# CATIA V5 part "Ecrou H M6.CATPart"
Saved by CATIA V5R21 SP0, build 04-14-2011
Part number: Ecrou H M6
Material "Acier": density 7860 kg/m3, Young's modulus 2e+11 Pa, Poisson ratio 0.266, thermal expansion 1.17e-05 1/K
Bounding box of the stored display mesh (mm): x -4 to 4, y -4.619 to 4.619, z 0 to 3
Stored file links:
  C:\Users\Olivier\Desktop\redaction CATIA (local)\CATIA\DONNEES\Exercice mise en plan 2 (Pompe de ventilation)\Pompe de ventilation (Product inclus)\Ecrou H M6.CATPart
  C:\Program Files\Dassault Systemes\B21\win_b64\startup\materials\French\Catalog.CATMaterial
  C:\Users\Olivier\Desktop\redaction CATIA (local)\CATIA\DONNEES\Exercice mise en plan 2 (Pompe de ventilation)\Pompe de ventilation (Product inclus)\CATIA_EnvironmentMap_Satin_512x512.jpg
  C:\Users\Olivier\Desktop\redaction CATIA (local)\pompe à moteur de ventilation refait\Pompe_a_moteur_de_ventilation.CATProduct
  C:\Users\Olivier\Desktop\redaction CATIA (local)\pompe à moteur de ventilation refait\Ecrou a collerette M5.CATPart
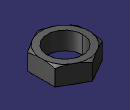
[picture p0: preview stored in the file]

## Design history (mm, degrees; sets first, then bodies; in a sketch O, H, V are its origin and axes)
Body1 (main body), material "Acier"
  Sketch1 on xy-plane, origin (0, 0, 0), H (1, 0, 0), V (0, 1, 0)
    circle A1 centre (0, 0) radius 3
    point P1 (4, -2.3094)
    point P2 (4, 2.3094)
    point P3 (0, 4.6188)
    point P4 (-4, 2.3094)
    point P5 (-4, -2.3094)
    point P6 (0, -4.6188)
    point P7 (4, 0)
    line L1 (4, -2.3094) -> (4, 2.3094)
    line L2 (4, 2.3094) -> (0, 4.6188)
    line L3 (0, 4.6188) -> (-4, 2.3094)
    line L4 (-4, 2.3094) -> (-4, -2.3094)
    line L5 (-4, -2.3094) -> (0, -4.6188)
    line L6 (0, -4.6188) -> (4, -2.3094)
    construction line L7 (0, 0) -> (4, 0)
    construction circle A2 centre (0, 0) radius 4.6188
    construction arc A3 centre (-4, -2.3094) radius 4.6188 from (-4, 2.3094) to (0, -4.6188) cw
    construction arc A4 centre (4, 2.3094) radius 4.6188 from (0, 4.6188) to (4, -2.3094) ccw
    distance L1 L4 = 8
    horizontal: L7 H
    coincidence: A2 P1, A2 P2, A2 P3, A2 P4, A2 P5, A2 P6, A3 O, A4 O
    midpoint: P7 L1
    parallelism: L1 L4
  Pad1: profile Sketch1, direction (0, 0, 1), length 3
  Sketch2 on yz-plane, origin (0, 0, 0), H (0, 1, 0), V (0, 0, 1)
    line L1 (3.8458, 3.1016) -> (4.7183, 2.6279)
    line L2 (4.7183, 2.6279) -> (4.7183, 3.1016)
    line L3 (4.7183, 3.1016) -> (3.8458, 3.1016)
    vertical: L2 V
    horizontal: L3 H
  Groove1: profile Sketch2, axis Sketch2.V, angle 360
